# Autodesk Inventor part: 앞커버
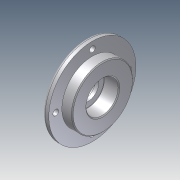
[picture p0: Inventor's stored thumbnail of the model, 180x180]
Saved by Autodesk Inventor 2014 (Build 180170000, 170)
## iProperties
Company: 한국ATC센터
Created: 2014-01
Part Number: 앞커버
Document SubType Name: Modeling
Designer: KYOUNG IL JANG
Density: 1 g/cm^3
Material: 알루미늄 6061
Mass: 88.8969 g
Surface Area: 235.103 cm^2
Volume: 88.8969 cm^3
Vendor: CBT Solutions
Appearance: 알루미늄 - 평지
Author: KYOUNG IL JANG
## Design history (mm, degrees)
sketch "스케치1"
  geometry: L1 (-15, -35)-(-15, 35) reference; L2 (-15, 35)-(67, 35) reference; L3 (-3, 25)-(-3, -10.613) reference; L4 (0, 0)-(-32, 0); L5 (-3, 0)-(-3, 35); L6 (-3, 35)-(-15, 35); L7 (-15, 35)-(-15, 50); L8 (-15, 50)-(-22, 50); L9 (-22, 50)-(-22, 22.5); L10 (-22, 22.5)-(-32, 22.5); L11 (-32, 22.5)-(-32, 0); L12 (-3, 18.5)-(-20, 18.5); L13 (-20, 18.5)-(-20, 12.5); L14 (-20, 12.5)-(-24, 12.5); L15 (-24, 12.5)-(-24, 16); L16 (-24, 16)-(-32, 16)
  constraints: 28 end point, 7 perpendicular, 6 parallel, 5 point on line, 1 horizontal, 1 other
  dimensions: "d0" = 7 distance of L7.end L8.end; "d1" = 45 diameter of L10 L4; "d2" = 10 distance of L9.end L10.end; "d3" = 37 diameter of L12 L4; "d4" = 17 distance of L12.start L12.end; "d5" = 32 diameter of L16 L4; "d6" = 8 distance of L15.end L16.end; "d7" = 25 diameter of L14 L4; "d8" = 100 diameter of L8 L4
revolve "회전1" sketch "스케치1" stored, may be unused: angle "d9" = 90 deg
fillet "모깎기1" dims "d10" = 3, "d11" = 0.3
chamfer "모따기1" distance "d12" = 1; stored, may be unused: second distance "d13" = 2, angle "d14" = 45 deg
sketch "스케치2"
  geometry: 2 further points
  constraints: 1 vertical alignment
  dimensions: "d15" = 42 distance of point (0, 0) point (0, 42)
hole "구멍1" sketch "스케치2" at (0, 42) diameter "d16" = 6.6; stored, may be unused: countersink angle "d20" = 90 deg, drill point angle "d22" = 118 deg; dims "d17" = 6, "d18" = 4, "d19" = 2, "d21" = 8
node "솔리드1"
pattern_circular "원형 패턴1" dims angle "d24" = 360 deg
node "참조1"
node "참조2"
